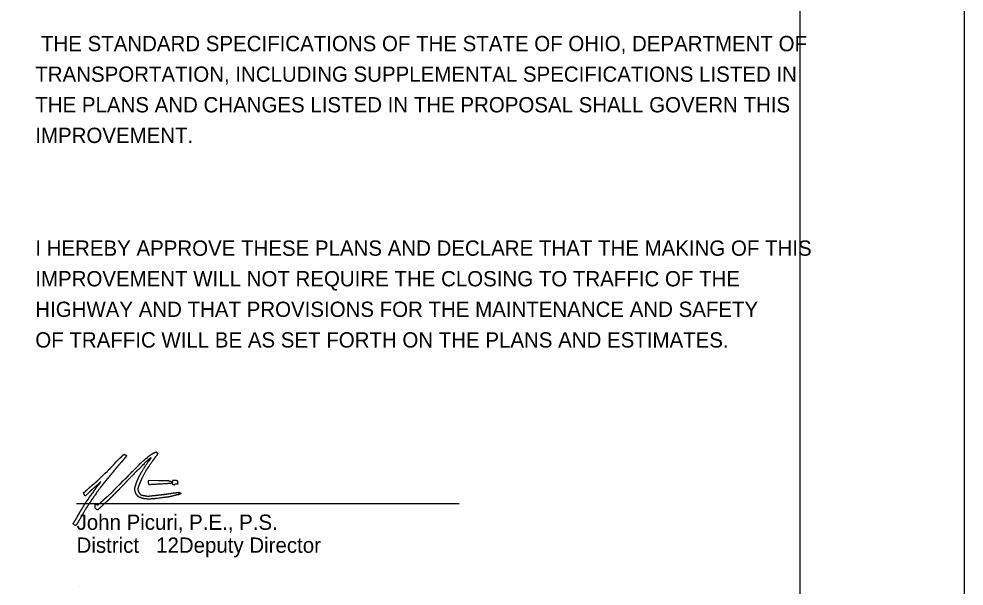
# Model space of a CAD drawing. Extents: x -6.1 to 38, y -7.7 to 22.
# Drawn here: x 24.85 to 33.5, y 5.9 to 11.09 of the extents above; entities that cross this region are included whole.
import ezdxf

# ---------------------------------------------------------------- set-up
doc = ezdxf.new("R2010")
doc.units = 0
for name, color, linetype in [('SH_Border', 7, 'Continuous'), ('SH_Data', 7, 'Continuous'), ('SH_Text', 7, 'Continuous')]:
    doc.layers.add(name, color=color, linetype=linetype)

msp = doc.modelspace()

# ---------------------------------------------------------------- linework, layer by layer
at = {"layer": 'SH_Border'}
msp.add_line((32, 0.5), (32, 21.5), dxfattribs=at)
msp.add_lwpolyline([(1.5, 21.5), (33.5, 21.5), (33.5, 0.5), (1.5, 0.5)], close=True, dxfattribs=at)
at = {"layer": 'SH_Data'}
for p, q in [((25, 9.0605), (25, 9.0605)), ((25.3777, 6.6523), (28.8777, 6.6523)), ((25.4051, 5.8978), (25.4051, 5.8978))]:
    msp.add_line(p, q, dxfattribs=at)
at = {"layer": 'SH_Text'}
for p, q in [((26.0341, 6.8383), (26.0341, 6.8383)), ((26.257, 6.8315), (26.257, 6.8315)), ((25.5526, 6.6059), (25.5526, 6.6059)), ((25.3617, 6.4544), (25.3617, 6.4544))]:
    msp.add_line(p, q, dxfattribs=at)
for points in [[(25.8025, 7.0949), (25.8134, 7.1055), (25.823, 7.0998)], [(25.5965, 6.8474), (25.5999, 6.8538), (25.5935, 6.8474)], [(26.1268, 6.8622), (26.0362, 6.8627), (26.0335, 6.8548)], [(26.2786, 6.8629), (26.2568, 6.8634), (26.2539, 6.8497)], [(26.2923, 6.833), (26.3071, 6.833), (26.3054, 6.8461)]]:
    msp.add_lwpolyline(points, dxfattribs=at)
for points in [[(25.761, 7.0556), (25.7779, 7.0714), (25.7966, 7.089), (25.8025, 7.0949)], [(25.823, 7.0998), (25.8345, 7.093), (25.8352, 7.0869), (25.8254, 7.0762)], [(26.0279, 7.0743), (26.0279, 7.0796), (26.0539, 7.0987), (26.08, 7.1127)], [(26.08, 7.1127), (26.1026, 7.1248), (26.1077, 7.1248), (26.1174, 7.1132)], [(26.1111, 7.0942), (26.1111, 7.0929), (26.1068, 7.0873), (26.1015, 7.0817)], [(26.1163, 7.1023), (26.1134, 7.0992), (26.1111, 7.0955), (26.1111, 7.0942)], [(26.1174, 7.1132), (26.1208, 7.109), (26.1207, 7.1072), (26.1163, 7.1023)], [(25.7079, 6.9994), (25.7202, 7.0123), (25.7303, 7.0238), (25.7303, 7.025)], [(25.7303, 7.025), (25.7303, 7.0261), (25.7441, 7.0399), (25.761, 7.0556)], [(25.7879, 7.0314), (25.7765, 7.0193), (25.7457, 6.9839), (25.735, 6.9706)], [(25.8054, 7.0524), (25.7984, 7.0437), (25.7905, 7.0342), (25.7879, 7.0314)], [(25.8254, 7.0762), (25.8214, 7.0718), (25.8124, 7.0611), (25.8054, 7.0524)], [(25.8486, 6.9045), (25.9189, 6.9781), (26.0109, 7.0663), (26.0197, 7.0685)], [(25.9686, 6.9333), (25.9805, 6.9557), (26.0359, 7.0401), (26.0424, 7.0458)], [(25.9959, 7.0176), (25.9959, 7.0138), (25.9873, 7.0058), (25.9833, 7.0058)], [(26.0113, 7.0336), (26.0029, 7.0263), (25.9959, 7.0191), (25.9959, 7.0176)], [(26.0599, 7.0712), (26.0599, 7.0734), (26.0348, 7.054), (26.0113, 7.0336)], [(26.0197, 7.0685), (26.0242, 7.0696), (26.0279, 7.0723), (26.0279, 7.0743)], [(26.0502, 7.009), (26.0353, 6.987), (26.0225, 6.9683), (26.0215, 6.9674)], [(26.0424, 7.0458), (26.047, 7.0499), (26.0599, 7.0686), (26.0599, 7.0712)], [(26.0879, 7.0617), (26.0798, 7.0527), (26.0766, 7.0483), (26.0502, 7.009)], [(26.0919, 7.0688), (26.0919, 7.0674), (26.0901, 7.0642), (26.0879, 7.0617)], [(26.1015, 7.0817), (26.0962, 7.0761), (26.0919, 7.0703), (26.0919, 7.0688)], [(25.6206, 6.9121), (25.6371, 6.9283), (25.6536, 6.9425), (25.6571, 6.9436)], [(25.6571, 6.9436), (25.6607, 6.9447), (25.6627, 6.9464), (25.6618, 6.9474)], [(25.6618, 6.9474), (25.6608, 6.9484), (25.6635, 6.9524), (25.6677, 6.9564)], [(25.6677, 6.9564), (25.672, 6.9603), (25.6747, 6.9643), (25.6738, 6.9652)], [(25.6738, 6.9652), (25.6729, 6.9661), (25.6752, 6.9678), (25.6788, 6.969)], [(25.6788, 6.969), (25.6825, 6.9701), (25.6855, 6.9722), (25.6855, 6.9735)], [(25.6855, 6.9735), (25.6855, 6.9749), (25.6955, 6.9866), (25.7079, 6.9994)], [(25.7128, 6.9434), (25.7071, 6.9364), (25.6954, 6.922), (25.6869, 6.9114)], [(25.735, 6.9706), (25.7285, 6.9627), (25.7186, 6.9505), (25.7128, 6.9434)], [(25.9441, 6.9642), (25.9421, 6.9642), (25.9114, 6.9331), (25.8417, 6.8604)], [(25.9798, 7.0034), (25.9797, 7.0005), (25.9466, 6.9642), (25.9441, 6.9642)], [(25.954, 6.9066), (25.9556, 6.9093), (25.9622, 6.9213), (25.9686, 6.9333)], [(26.0215, 6.9674), (26.0147, 6.961), (25.9751, 6.8851), (25.9623, 6.8538)], [(25.9833, 7.0058), (25.9814, 7.0058), (25.9798, 7.0048), (25.9798, 7.0034)], [(25.528, 6.826), (25.5454, 6.8401), (25.5794, 6.8717), (25.6206, 6.9121)], [(25.5935, 6.8474), (25.5817, 6.8355), (25.5591, 6.8151), (25.5351, 6.7946)], [(25.5838, 6.8314), (25.589, 6.8367), (25.5947, 6.8439), (25.5965, 6.8474)], [(25.6373, 6.8522), (25.6364, 6.8514), (25.6288, 6.8417), (25.6205, 6.8308)], [(25.6516, 6.8698), (25.6447, 6.861), (25.6383, 6.8531), (25.6373, 6.8522)], [(25.6678, 6.889), (25.6658, 6.8873), (25.6585, 6.8786), (25.6516, 6.8698)], [(25.6869, 6.9114), (25.6784, 6.9009), (25.6698, 6.8908), (25.6678, 6.889)], [(25.8417, 6.8604), (25.8165, 6.8341), (25.7807, 6.7973), (25.7623, 6.7786)], [(25.7762, 6.8314), (25.7826, 6.8367), (25.7879, 6.8425), (25.7879, 6.8443)], [(25.7879, 6.8443), (25.7879, 6.8461), (25.7968, 6.8554), (25.8078, 6.8651)], [(25.8078, 6.8651), (25.8187, 6.8748), (25.8371, 6.8925), (25.8486, 6.9045)], [(25.9156, 6.8113), (25.9172, 6.8153), (25.9209, 6.8266), (25.9239, 6.8362)], [(25.9239, 6.8362), (25.9288, 6.8526), (25.9473, 6.8956), (25.954, 6.9066)], [(25.954, 6.8346), (25.9412, 6.8072), (25.938, 6.7711), (25.947, 6.7569)], [(25.9623, 6.8538), (25.9594, 6.8468), (25.9557, 6.8382), (25.954, 6.8346)], [(26.0335, 6.8548), (26.032, 6.8502), (26.0322, 6.8432), (26.0341, 6.8383)], [(26.0341, 6.8383), (26.0379, 6.8282), (26.041, 6.8281), (26.1335, 6.833)], [(26.2211, 6.8594), (26.2191, 6.8607), (26.1767, 6.8619), (26.1268, 6.8622)], [(26.1335, 6.833), (26.235, 6.8385), (26.272, 6.8459), (26.2382, 6.8538)], [(26.2382, 6.8538), (26.2308, 6.8556), (26.223, 6.8581), (26.2211, 6.8594)], [(26.2539, 6.8497), (26.2513, 6.838), (26.2518, 6.8354), (26.257, 6.8315)], [(26.302, 6.8608), (26.3011, 6.8617), (26.2906, 6.8627), (26.2786, 6.8629)], [(26.3054, 6.8461), (26.3044, 6.8533), (26.3029, 6.8599), (26.302, 6.8608)], [(25.4471, 6.7369), (25.4407, 6.7493), (25.441, 6.7554), (25.4481, 6.7577)], [(25.4932, 6.7562), (25.4621, 6.7248), (25.455, 6.7218), (25.4471, 6.7369)], [(25.4481, 6.7577), (25.4513, 6.7587), (25.4634, 6.7685), (25.475, 6.7795)], [(25.475, 6.7795), (25.4963, 6.7997), (25.5019, 6.8047), (25.528, 6.826)], [(25.5351, 6.7946), (25.5219, 6.7834), (25.503, 6.7661), (25.4932, 6.7562)], [(25.5201, 6.7447), (25.5212, 6.7475), (25.5236, 6.7498), (25.5254, 6.7498)], [(25.5254, 6.7498), (25.5272, 6.7498), (25.5287, 6.752), (25.5287, 6.7546)], [(25.5287, 6.7546), (25.5287, 6.7573), (25.5301, 6.7594), (25.5319, 6.7594)], [(25.5319, 6.7594), (25.5336, 6.7594), (25.5351, 6.7615), (25.5351, 6.764)], [(25.5351, 6.764), (25.5351, 6.7665), (25.5369, 6.7705), (25.5392, 6.7728)], [(25.5392, 6.7728), (25.5508, 6.7848), (25.561, 6.8012), (25.5588, 6.8046)], [(25.6012, 6.8068), (25.5945, 6.8001), (25.5543, 6.7437), (25.5543, 6.7411)], [(25.5588, 6.8046), (25.5574, 6.8069), (25.5578, 6.8076), (25.5598, 6.8064)], [(25.5598, 6.8064), (25.5617, 6.8052), (25.5657, 6.8083), (25.5688, 6.8131)], [(25.5688, 6.8131), (25.5719, 6.8179), (25.5787, 6.8262), (25.5838, 6.8314)], [(25.6205, 6.8308), (25.6122, 6.8199), (25.6035, 6.8091), (25.6012, 6.8068)], [(25.6623, 6.7194), (25.675, 6.7306), (25.7206, 6.7758), (25.7466, 6.8031)], [(25.7623, 6.7786), (25.7438, 6.7599), (25.7154, 6.7308), (25.6991, 6.714)], [(25.7466, 6.8031), (25.7564, 6.8134), (25.7698, 6.8262), (25.7762, 6.8314)], [(25.9174, 6.7526), (25.9121, 6.7647), (25.9111, 6.7999), (25.9156, 6.8113)], [(25.9796, 6.7006), (25.9539, 6.7082), (25.9269, 6.7307), (25.9174, 6.7526)], [(25.947, 6.7569), (25.9598, 6.7369), (25.9731, 6.7295), (26.0057, 6.7241)], [(26.2311, 6.7447), (26.2439, 6.7467), (26.2739, 6.7507), (26.2839, 6.7517)], [(26.257, 6.8315), (26.264, 6.8262), (26.2775, 6.8251), (26.2775, 6.8298)], [(26.2775, 6.8298), (26.2775, 6.8316), (26.2841, 6.833), (26.2923, 6.833)], [(26.2839, 6.7517), (26.2883, 6.7522), (26.2919, 6.7528), (26.2919, 6.7531)], [(26.2919, 6.7531), (26.2919, 6.7533), (26.2991, 6.7541), (26.3079, 6.7547)], [(26.3079, 6.7547), (26.3196, 6.7556), (26.3217, 6.7552), (26.3159, 6.7532)], [(26.3159, 6.7532), (26.3086, 6.7507), (26.309, 6.7505), (26.3199, 6.7502)], [(26.3199, 6.7502), (26.3265, 6.75), (26.3319, 6.7484), (26.3319, 6.7466)], [(25.458, 6.6551), (25.4626, 6.6619), (25.4681, 6.6709), (25.4704, 6.6751)], [(25.4704, 6.6751), (25.4727, 6.6792), (25.476, 6.6826), (25.4776, 6.6826)], [(25.4776, 6.6826), (25.4793, 6.6826), (25.4807, 6.6848), (25.4807, 6.6874)], [(25.4807, 6.6874), (25.4807, 6.6901), (25.4819, 6.6922), (25.4834, 6.6922)], [(25.4834, 6.6922), (25.4848, 6.6922), (25.4898, 6.6992), (25.4944, 6.7076)], [(25.5224, 6.6954), (25.5212, 6.6946), (25.5084, 6.6758), (25.494, 6.6538)], [(25.4944, 6.7076), (25.499, 6.7161), (25.5062, 6.7267), (25.5105, 6.7313)], [(25.5105, 6.7313), (25.5147, 6.7358), (25.519, 6.7419), (25.5201, 6.7447)], [(25.5286, 6.7048), (25.5264, 6.7006), (25.5235, 6.6963), (25.5224, 6.6954)], [(25.5356, 6.716), (25.534, 6.7142), (25.5309, 6.7091), (25.5286, 6.7048)], [(25.5543, 6.7411), (25.5543, 6.739), (25.5509, 6.7345), (25.5356, 6.716)], [(25.5943, 6.6591), (25.6048, 6.669), (25.622, 6.6844), (25.6324, 6.6934)], [(25.6598, 6.6758), (25.6544, 6.6717), (25.6396, 6.6583), (25.6269, 6.6461)], [(25.6324, 6.6934), (25.6428, 6.7025), (25.6563, 6.7142), (25.6623, 6.7194)], [(25.6991, 6.714), (25.6828, 6.6972), (25.6651, 6.68), (25.6598, 6.6758)], [(26.1063, 6.6987), (26.0655, 6.6936), (25.9999, 6.6946), (25.9796, 6.7006)], [(26.0057, 6.7241), (26.0264, 6.7207), (26.0378, 6.7211), (26.0935, 6.7272)], [(26.0935, 6.7272), (26.1495, 6.7333), (26.1995, 6.7396), (26.2311, 6.7447)], [(26.2775, 6.7271), (26.2398, 6.7169), (26.2006, 6.7103), (26.1063, 6.6987)], [(26.3084, 6.7338), (26.3046, 6.7337), (26.2907, 6.7308), (26.2775, 6.7271)], [(26.3202, 6.7386), (26.3176, 6.736), (26.3123, 6.7338), (26.3084, 6.7338)], [(26.3284, 6.7434), (26.3266, 6.7434), (26.3228, 6.7413), (26.3202, 6.7386)], [(26.3319, 6.7466), (26.3319, 6.7449), (26.3303, 6.7434), (26.3284, 6.7434)], [(25.4007, 6.559), (25.4007, 6.5611), (25.4053, 6.5701), (25.4111, 6.579)], [(25.4111, 6.579), (25.4168, 6.5879), (25.4235, 6.5987), (25.426, 6.6029)], [(25.426, 6.6029), (25.4431, 6.6317), (25.4508, 6.6442), (25.458, 6.6551)], [(25.465, 6.6105), (25.4625, 6.6073), (25.4582, 6.5999), (25.437, 6.5618)], [(25.494, 6.6538), (25.4795, 6.6318), (25.4665, 6.6123), (25.465, 6.6105)], [(25.5526, 6.6059), (25.5488, 6.6102), (25.547, 6.6167), (25.5473, 6.6254)], [(25.5473, 6.6254), (25.548, 6.6431), (25.55, 6.6452), (25.5635, 6.6431)], [(25.6269, 6.6461), (25.5793, 6.6003), (25.5648, 6.5925), (25.5526, 6.6059)], [(25.5635, 6.6431), (25.5742, 6.6414), (25.5766, 6.6426), (25.5943, 6.6591)], [(25.3515, 6.4632), (25.347, 6.4701), (25.3476, 6.4718), (25.3612, 6.4926)], [(25.3612, 6.4926), (25.3692, 6.5047), (25.3802, 6.5233), (25.3857, 6.5338)], [(25.3943, 6.4888), (25.3943, 6.4852), (25.3712, 6.4522), (25.3689, 6.4526)], [(25.3857, 6.5338), (25.3911, 6.5444), (25.3967, 6.5535), (25.3981, 6.5541)], [(25.4039, 6.5055), (25.3986, 6.4977), (25.3943, 6.4902), (25.3943, 6.4888)], [(25.3981, 6.5541), (25.3995, 6.5547), (25.4007, 6.5569), (25.4007, 6.559)], [(25.4135, 6.5213), (25.4135, 6.5204), (25.4091, 6.5134), (25.4039, 6.5055)], [(25.421, 6.5347), (25.4168, 6.5281), (25.4135, 6.5221), (25.4135, 6.5213)], [(25.437, 6.5618), (25.4323, 6.5535), (25.4251, 6.5413), (25.421, 6.5347)], [(25.3617, 6.4544), (25.3588, 6.4552), (25.3542, 6.4591), (25.3515, 6.4632)], [(25.3689, 6.4526), (25.3679, 6.4528), (25.3647, 6.4536), (25.3617, 6.4544)]]:
    msp.add_open_spline(points, degree=2, dxfattribs=at)

# ---------------------------------------------------------------- texts
at = {"layer": 'SH_Data'}
for s, p in [('I HEREBY APPROVE THESE PLANS AND DECLARE THAT THE MAKING OF THIS', (25, 8.9205)), ('IMPROVEMENT WILL NOT REQUIRE THE CLOSING TO TRAFFIC OF THE', (25, 8.6405)), ('HIGHWAY AND THAT PROVISIONS FOR THE MAINTENANCE AND SAFETY', (25, 8.3605))]:
    msp.add_text(s, height=0.14, dxfattribs=at).set_placement(p)
at = {"layer": 'SH_Text'}
for s, p in [(' THE STANDARD SPECIFICATIONS OF THE STATE OF OHIO, DEPARTMENT OF', (25, 10.7925)), ('TRANSPORTATION, INCLUDING SUPPLEMENTAL SPECIFICATIONS LISTED IN', (25, 10.5125)), ('THE PLANS AND CHANGES LISTED IN THE PROPOSAL SHALL GOVERN THIS', (25, 10.2325)), ('IMPROVEMENT.', (25, 9.9525)), ('OF TRAFFIC WILL BE AS SET FORTH ON THE PLANS AND ESTIMATES.', (25, 8.0805)), ('John Picuri, P.E., P.S.', (25.3777, 6.4123)), ('District       Deputy Director', (25.3777, 6.2023)), ('              12', (25.3777, 6.2023))]:
    msp.add_text(s, height=0.14, dxfattribs=at).set_placement(p)

doc.saveas('drawing.dxf')
